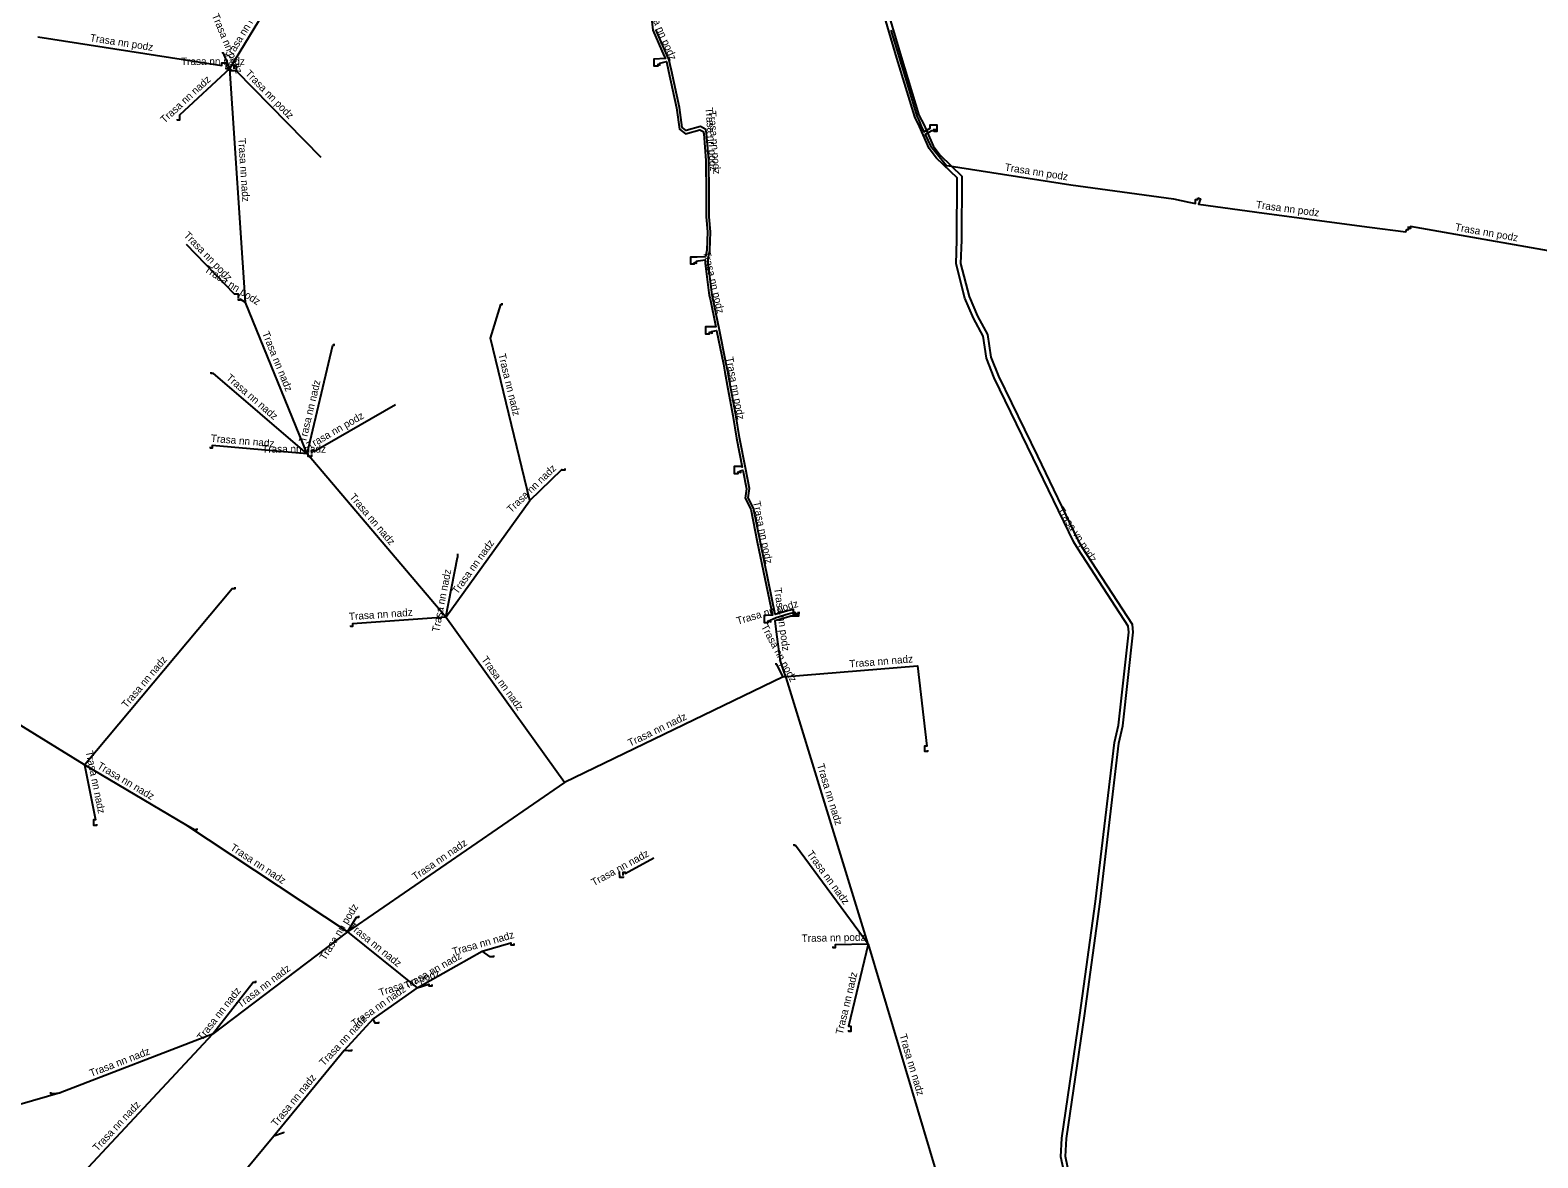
# Model space of a CAD drawing. Extents: x -742082 to -717476, y -1040737 to -1024597.
# Drawn here: x -736206.3 to -736004.4, y -1032268.1 to -1032117.1 of the extents above; entities that cross this region are included whole.
import ezdxf

# ---------------------------------------------------------------- set-up
doc = ezdxf.new("R2010")
doc.units = 0
for name, color, linetype in [('Level 13', 7, 'Continuous'), ('Level 14', 7, 'Continuous'), ('Level 15', 7, 'Continuous'), ('Level 20', 7, 'Continuous'), ('Level 25', 7, 'Continuous')]:
    doc.layers.add(name, color=color, linetype=linetype)

msp = doc.modelspace()

# ---------------------------------------------------------------- linework, layer by layer
at = {"layer": 'Level 13'}
for p, q in [((-736177.51, -1032153.54), (-736179.61, -1032122.24)), ((-736169.24, -1032173.82), (-736177.51, -1032153.54)), ((-736150.66, -1032195.7), (-736169.24, -1032173.82)), ((-736150.66, -1032195.7), (-736149.1, -1032187.7)), ((-736134.77, -1032217.84), (-736150.66, -1032195.7)), ((-736105.47, -1032203.68), (-736134.77, -1032217.84)), ((-736094.1, -1032239.5), (-736105.11, -1032203.78)), ((-736134.77, -1032217.84), (-736163.82, -1032237.82)), ((-736163.82, -1032237.82), (-736181.93, -1032251.54)), ((-736094.1, -1032239.5), (-736083.14, -1032276.17)), ((-736181.93, -1032251.54), (-736203.41, -1032274.54))]:
    msp.add_line(p, q, dxfattribs=at)
for points in [[(-736179.61, -1032122.24), (-736179.84, -1032122.11), (-736179.84, -1032122.26), (-736180.1, -1032122.26), (-736180.1, -1032122.1)], [(-736179, -1032122.4), (-736179, -1032122.56), (-736179.35, -1032122.56), (-736179.61, -1032122.24)], [(-736169.24, -1032173.82), (-736169.15, -1032173.8), (-736169.15, -1032174.16), (-736168.6, -1032174.16), (-736168.6, -1032173.9)], [(-736149.1, -1032187.2), (-736149.1, -1032187.36), (-736149.1, -1032187.7)], [(-736184, -1032224), (-736184, -1032224.16), (-736184.31, -1032224.16), (-736185.5, -1032223.5)], [(-736126.9, -1032230.4), (-736126.9, -1032230.57), (-736127.35, -1032230.56), (-736127.4, -1032229.77)], [(-736144.3, -1032241), (-736144.3, -1032241.16), (-736144.75, -1032241.16), (-736145.8, -1032240.4)], [(-736159.7, -1032249.9), (-736159.7, -1032250.06), (-736160.15, -1032250.06), (-736160.4, -1032249.5)], [(-736163.3, -1032253.6), (-736163.3, -1032253.76), (-736163.75, -1032253.76), (-736164.3, -1032253.7)], [(-736203.6, -1032259.3), (-736203.6, -1032259.46), (-736203.34, -1032259.46), (-736202.3, -1032259.4)], [(-736172.4, -1032264.6), (-736172.4, -1032264.76), (-736173.7, -1032265.2)]]:
    msp.add_lwpolyline(points, dxfattribs=at)
at = {"layer": 'Level 14'}
for p, q in [((-736179.61, -1032122.24), (-736172.05, -1032109.83)), ((-736150.66, -1032195.7), (-736139.42, -1032180.08)), ((-736199.06, -1032215.49), (-736219.52, -1032202.89)), ((-736185.5, -1032223.5), (-736199.06, -1032215.49)), ((-736163.82, -1032237.82), (-736185.5, -1032223.5)), ((-736163.82, -1032237.82), (-736154.51, -1032245.34)), ((-736154.51, -1032245.34), (-736145.8, -1032240.4)), ((-736154.51, -1032245.34), (-736160.4, -1032249.5)), ((-736160.4, -1032249.5), (-736164.3, -1032253.7)), ((-736181.93, -1032251.54), (-736202.3, -1032259.4)), ((-736164.3, -1032253.7), (-736173.7, -1032265.2))]:
    msp.add_line(p, q, dxfattribs=at)
for points in [[(-736179.61, -1032122.24), (-736186.34, -1032128.47), (-736186.34, -1032129.16), (-736186.6, -1032129.16), (-736186.6, -1032129)], [(-736139.42, -1032180.08), (-736144.69, -1032158.33), (-736143.31, -1032153.83), (-736143.1, -1032153.83), (-736143.1, -1032153.67)], [(-736169.24, -1032173.82), (-736165.79, -1032159.26), (-736165.6, -1032159.26), (-736165.6, -1032159.1)], [(-736169.24, -1032173.82), (-736181.84, -1032163.01), (-736181.84, -1032163.06), (-736182.1, -1032163.06), (-736182.1, -1032162.9)], [(-736169.24, -1032173.82), (-736181.95, -1032172.73), (-736181.95, -1032173.06), (-736182.2, -1032173.06), (-736182.2, -1032172.9)], [(-736139.42, -1032180.08), (-736135.15, -1032175.94), (-736135.15, -1032175.96), (-736134.7, -1032175.96), (-736134.7, -1032175.8)], [(-736199.06, -1032215.49), (-736179.3, -1032191.86), (-736178.9, -1032191.86), (-736178.9, -1032191.7)], [(-736150.66, -1032195.7), (-736163.15, -1032196.58), (-736163.15, -1032196.96), (-736163.4, -1032196.96), (-736163.4, -1032196.8)], [(-736105.47, -1032203.68), (-736087.5, -1032202.2), (-736086.24, -1032212.95), (-736086.55, -1032212.95), (-736086.55, -1032213.66), (-736086.1, -1032213.66), (-736086.1, -1032213.5)], [(-736199.06, -1032215.49), (-736197.57, -1032222.85), (-736197.85, -1032222.85), (-736197.85, -1032223.56), (-736197.4, -1032223.56), (-736197.4, -1032223.4)], [(-736094.1, -1032239.5), (-736103.84, -1032226.26), (-736104, -1032226.26), (-736104, -1032226.1)], [(-736126.9, -1032230.29), (-736126.9, -1032229.85), (-736126.64, -1032229.85), (-736126.64, -1032230), (-736122.8, -1032227.9)], [(-736145.8, -1032240.4), (-736141.95, -1032239.3), (-736141.95, -1032239.56), (-736141.5, -1032239.56), (-736141.5, -1032239.4)], [(-736094.1, -1032239.5), (-736096.72, -1032250.45), (-736096.44, -1032250.45), (-736096.44, -1032251.16), (-736096.7, -1032251.16), (-736096.7, -1032251)], [(-736181.93, -1032251.54), (-736176.48, -1032244.56), (-736176.1, -1032244.56), (-736176.1, -1032244.4)], [(-736202.3, -1032259.4), (-736215.15, -1032263.1), (-736215.15, -1032263.56), (-736215.4, -1032263.56), (-736215.4, -1032263.4)], [(-736173.7, -1032265.2), (-736183.61, -1032277.15), (-736183.55, -1032277.15), (-736183.55, -1032277.86), (-736183.8, -1032277.86), (-736183.8, -1032277.7)]]:
    msp.add_lwpolyline(points, dxfattribs=at)
at = {"layer": 'Level 15'}
for points in [[(-736123.53, -1032114.91), (-736123.18, -1032115.07), (-736122.95, -1032117.1), (-736121.44, -1032120.56), (-736121.26, -1032120.9), (-736122.79, -1032120.96), (-736122.79, -1032121.87), (-736122.24, -1032121.87), (-736122.24, -1032121.61)], [(-736103.46, -1032194.96), (-736103.46, -1032195.42), (-736104.12, -1032195.42), (-736104.12, -1032194.65), (-736104.93, -1032194.85), (-736106.57, -1032195.34), (-736109.46, -1032181.1), (-736110.18, -1032179.7), (-736109.98, -1032178.48), (-736110.53, -1032175.71), (-736111.35, -1032171.66), (-736111.82, -1032168.61), (-736112.49, -1032165.06), (-736112.92, -1032162.8), (-736113.11, -1032161.76), (-736114.08, -1032157.05), (-736114.89, -1032153), (-736115, -1032152.55), (-736115.53, -1032148.3), (-736115.53, -1032147.63), (-736115.33, -1032146.61), (-736115.22, -1032144.08), (-736115.41, -1032142.09), (-736115.42, -1032139.01), (-736115.46, -1032134.51), (-736115.74, -1032130.92), (-736115.86, -1032130.39), (-736116.58, -1032129.99), (-736118.5, -1032130.54), (-736119.01, -1032130.14), (-736119.38, -1032127.44), (-736120.45, -1032122.5), (-736120.78, -1032120.96), (-736121.07, -1032120.39), (-736122.56, -1032116.99)], [(-736091.09, -1032117.08), (-736089.16, -1032123.38), (-736087.59, -1032128.59), (-736087.33, -1032129.16), (-736087.01, -1032129.93), (-736086.64, -1032130.71), (-736085.81, -1032130.23), (-736085.81, -1032129.76), (-736084.89, -1032129.76), (-736084.89, -1032130.67), (-736085.27, -1032130.67), (-736085.27, -1032130.3)], [(-736205.3, -1032118), (-736180.65, -1032121.83), (-736180.65, -1032121.45), (-736180.1, -1032121.45), (-736180.1, -1032121.99)], [(-736179.61, -1032122.24), (-736180.46, -1032120.19), (-736180.51, -1032120.19), (-736180.51, -1032120.03)], [(-736122.24, -1032121.61), (-736121.99, -1032121.77), (-736121.99, -1032121.52), (-736121.12, -1032121.27), (-736120.84, -1032122.58), (-736119.77, -1032127.51), (-736119.38, -1032130.35), (-736118.58, -1032130.98), (-736116.63, -1032130.42), (-736116.21, -1032130.66), (-736116.13, -1032130.98), (-736115.86, -1032134.53), (-736115.82, -1032139.02), (-736115.81, -1032142.11), (-736115.62, -1032144.09), (-736115.72, -1032146.57), (-736115.89, -1032147.43), (-736117, -1032147.49), (-736117.91, -1032147.49), (-736117.9, -1032148.4), (-736117.36, -1032148.4), (-736117.35, -1032148.14)], [(-736179, -1032122.29), (-736179, -1032121.85), (-736178.74, -1032121.85), (-736178.74, -1032122.56), (-736178.74, -1032122.56), (-736167.4, -1032134.1)], [(-736085.2, -1032130.3), (-736085.2, -1032130.57), (-736085.58, -1032130.57), (-736086.46, -1032131.07), (-736085.74, -1032132.58), (-736083.6, -1032135.23), (-736083.25, -1032135.26), (-736066.96, -1032137.8), (-736053.2, -1032139.68), (-736051.15, -1032140.13), (-736050.27, -1032140.31), (-736050.28, -1032139.79), (-736049.98, -1032139.79), (-736049.98, -1032139.53)], [(-736049.98, -1032139.53), (-736049.62, -1032139.69), (-736049.87, -1032140.38), (-736041.09, -1032141.58), (-736026.98, -1032143.47), (-736022.09, -1032144.11), (-736021.99, -1032143.77), (-736021.75, -1032143.77), (-736021.75, -1032143.4)], [(-735997.22, -1032146.99), (-735997.22, -1032147.26), (-735997.65, -1032147.26), (-735997.7, -1032147.57), (-736021.5, -1032143.37), (-736021.5, -1032143.67), (-736021.67, -1032143.67), (-736021.67, -1032143.4)], [(-736178.45, -1032152.97), (-736178.45, -1032152.43), (-736178.98, -1032152.43), (-736185.4, -1032145.8)], [(-736117.35, -1032148.14), (-736117.1, -1032148.3), (-736117.1, -1032148.04), (-736116.88, -1032147.97), (-736115.93, -1032147.84), (-736115.93, -1032148.32), (-736115.39, -1032152.62), (-736115.28, -1032153.08), (-736114.51, -1032156.84), (-736115.9, -1032156.84), (-736115.9, -1032157.75), (-736115.35, -1032157.75), (-736115.35, -1032157.49)], [(-736177.51, -1032153.54), (-736178.19, -1032153.1), (-736178.19, -1032153.23), (-736178.45, -1032153.23), (-736178.45, -1032153.08)], [(-736115.35, -1032157.49), (-736115, -1032157.65), (-736115.1, -1032157.43), (-736114.43, -1032157.32), (-736113.5, -1032161.84), (-736113.32, -1032162.88), (-736112.89, -1032165.13), (-736112.21, -1032168.68), (-736111.75, -1032171.73), (-736110.96, -1032175.61), (-736111.15, -1032175.53), (-736112.06, -1032175.53), (-736112.06, -1032176.44), (-736111.51, -1032176.44), (-736111.51, -1032176.18)], [(-736168.6, -1032173.79), (-736168.6, -1032173.35), (-736168.35, -1032173.35), (-736168.35, -1032173.5), (-736157.4, -1032167.2)], [(-736111.51, -1032176.18), (-736111.15, -1032176.34), (-736111.25, -1032176.1), (-736110.88, -1032176), (-736110.39, -1032178.49), (-736110.6, -1032179.77), (-736109.84, -1032181.24), (-736108.96, -1032185.59), (-736106.94, -1032195.42), (-736108.04, -1032195.49), (-736108.04, -1032196.4), (-736107.49, -1032196.4), (-736107.49, -1032196.14)], [(-736107.49, -1032196.14), (-736107.14, -1032196.3), (-736107.23, -1032196.09), (-736106.45, -1032195.72), (-736104.82, -1032195.24), (-736103.92, -1032195.01), (-736103.92, -1032195.22), (-736103.36, -1032195.22), (-736103.36, -1032194.96)], [(-736103.44, -1032194.96), (-736103.44, -1032195.57), (-736103.61, -1032195.57), (-736104.48, -1032195.57), (-736104.72, -1032195.63), (-736106.62, -1032196.19), (-736106.38, -1032198), (-736105.89, -1032201.6), (-736105.44, -1032202.94), (-736105.22, -1032203.57), (-736105.11, -1032203.78)], [(-736105.47, -1032203.68), (-736106.35, -1032202.02), (-736106.45, -1032202.02), (-736106.45, -1032201.86)], [(-736163.82, -1032237.82), (-736162.62, -1032235.86), (-736162.3, -1032235.86), (-736162.3, -1032235.7)], [(-736094.1, -1032239.5), (-736098.54, -1032239.59), (-736098.54, -1032239.96), (-736098.8, -1032239.96), (-736098.8, -1032239.8)], [(-736154.51, -1032245.34), (-736152.95, -1032244.82), (-736152.95, -1032245.06), (-736152.5, -1032245.06), (-736152.5, -1032244.9)]]:
    msp.add_lwpolyline(points, dxfattribs=at)
at = {"layer": 'Level 25'}
for points in [[(-736067.77, -1032270.43), (-736068.3, -1032267.95), (-736068.15, -1032265.46), (-736065.74, -1032249), (-736063.65, -1032233.75), (-736061.14, -1032212.46), (-736060.58, -1032210.15), (-736059.22, -1032197.72), (-736059.3, -1032196.89), (-736066, -1032186.61), (-736066.55, -1032185.67), (-736071.99, -1032174.41), (-736077.22, -1032163.66), (-736078.25, -1032161.03), (-736078.7, -1032158.05), (-736080.02, -1032155.68), (-736081.18, -1032152.96), (-736082.34, -1032148.4), (-736082.24, -1032145.22), (-736082.18, -1032136.89), (-736084.94, -1032134.23), (-736085.92, -1032132.92), (-736087.23, -1032129.99), (-736087.87, -1032128.7), (-736090.27, -1032120.85), (-736092.54, -1032113.13)], [(-736091.95, -1032112.95), (-736089.69, -1032120.67), (-736087.3, -1032128.47), (-736086.67, -1032129.73), (-736085.39, -1032132.6), (-736084.48, -1032133.82), (-736081.57, -1032136.63), (-736081.63, -1032145.23), (-736081.73, -1032148.33), (-736080.6, -1032152.76), (-736079.47, -1032155.41), (-736078.11, -1032157.85), (-736077.66, -1032160.87), (-736076.67, -1032163.41), (-736071.45, -1032174.15), (-736066.02, -1032185.39), (-736065.49, -1032186.3)], [(-736067.19, -1032270.26), (-736067.69, -1032267.9), (-736067.55, -1032265.52), (-736065.15, -1032249.09), (-736063.05, -1032233.82), (-736060.55, -1032212.57), (-736059.99, -1032210.25), (-736058.61, -1032197.72), (-736058.72, -1032196.69), (-736065.49, -1032186.3)]]:
    msp.add_lwpolyline(points, dxfattribs=at)

# ---------------------------------------------------------------- texts
at = {"layer": 'Level 20'}
for s, rotation, p in [('Trasa nn nadz', 58.6505, (-736179.53, -1032121.15)), ('Trasa nn podz', 293.5564, (-736124.01, -1032113.41)), ('Trasa nn podz', 292.5787, (-736182.03, -1032115.12)), ('Trasa nn podz', 351.1681, (-736198.38, -1032118.57)), ('Trasa nn nadz', 360, (-736186.13, -1032121.76)), ('Trasa nn nadz', 42.7765, (-736188.34, -1032129.63)), ('Trasa nn podz', 314.5145, (-736177.62, -1032122.99)), ('Trasa nn podz', 274.3455, (-736115.9, -1032127.49)), ('Trasa nn podz', 274.3462, (-736115.47, -1032127.91)), ('Trasa nn nadz', 273.8384, (-736178.48, -1032131.58)), ('Trasa nn podz', 351.1286, (-736075.87, -1032135.9)), ('Trasa nn podz', 352.3782, (-736042.22, -1032140.92)), ('Trasa nn podz', 314.087, (-736185.83, -1032144.64)), ('Trasa nn podz', 350.0101, (-736015.57, -1032143.91)), ('Trasa nn podz', 283.0678, (-736116.23, -1032146.8)), ('Trasa nn podz', 327.343, (-736183.1, -1032149.36)), ('Trasa nn nadz', 292.1852, (-736175.29, -1032157.67)), ('Trasa nn nadz', 283.6202, (-736143.65, -1032160.51)), ('Trasa nn podz', 280.7374, (-736113.17, -1032160.94)), ('Trasa nn nadz', 319.3695, (-736180.17, -1032163.79)), ('Trasa nn nadz', 76.6525, (-736169.41, -1032172.37)), ('Trasa nn podz', 29.9083, (-736168.94, -1032173.26)), ('Trasa nn nadz', 355.0984, (-736182.18, -1032172.21)), ('Trasa nn nadz', 44.1187, (-736141.92, -1032181.81)), ('Trasa nn nadz', 310.3372, (-736163.64, -1032179.64)), ('Trasa nn podz', 281.5863, (-736109.54, -1032180.26)), ('Trasa vn podz', 303.0777, (-736068.83, -1032181.35)), ('Trasa nn nadz', 54.2616, (-736149.12, -1032192.7)), ('Trasa nn nadz', 78.9658, (-736151.57, -1032197.77)), ('Trasa nn podz', 277.7247, (-736106.71, -1032191.82)), ('Trasa nn podz', 16.3249, (-736111.58, -1032196.7)), ('Trasa nn nadz', 4.0096, (-736163.61, -1032196.11)), ('Trasa nn podz', 298.0319, (-736108.48, -1032196.95)), ('Trasa nn nadz', 50.0982, (-736193.42, -1032207.96)), ('Trasa nn nadz', 305.6672, (-736145.97, -1032201.37)), ('Trasa nn nadz', 4.7117, (-736096.59, -1032202.45)), ('Trasa nn nadz', 25.791, (-736126, -1032213.05)), ('Trasa nn nadz', 281.4385, (-736198.91, -1032213.69)), ('Trasa nn nadz', 329.4293, (-736197.44, -1032215.87)), ('Trasa nn nadz', 287.1279, (-736100.98, -1032215.48)), ('Trasa nn nadz', 326.5546, (-736179.63, -1032226.78)), ('Trasa nn nadz', 34.5194, (-736154.76, -1032230.98)), ('Trasa nn nadz', 28.7061, (-736130.85, -1032231.74)), ('Trasa nn nadz', 306.3268, (-736102.39, -1032227.39)), ('Trasa nn podz', 58.5305, (-736166.8, -1032241.74)), ('Trasa nn nadz', 321.071, (-736163.74, -1032237.24)), ('Trasa nn nadz', 15.9454, (-736149.64, -1032240.98)), ('Trasa nn podz', 1.1932, (-736103.01, -1032239.19)), ('Trasa nn nadz', 29.5604, (-736155.87, -1032245.54)), ('Trasa nn nadz', 37.1473, (-736178.19, -1032248.08)), ('Trasa nn podz', 18.5258, (-736159.45, -1032246.47)), ('Trasa nn nadz', 76.5618, (-736097.52, -1032251.65)), ('Trasa nn nadz', 52.0225, (-736183.3, -1032252.48)), ('Trasa nn nadz', 35.2329, (-736162.88, -1032250.64)), ('Trasa nn nadz', 47.1211, (-736166.99, -1032255.87)), ('Trasa nn nadz', 286.6405, (-736089.94, -1032251.67)), ('Trasa nn nadz', 21.0997, (-736198.16, -1032257.27)), ('Trasa nn nadz', 50.7377, (-736173.37, -1032264)), ('Trasa nn nadz', 46.9572, (-736197.33, -1032267.29))]:
    msp.add_text(s, height=1, rotation=rotation, dxfattribs=at).set_placement(p)
msp.add_text('Trasa nn nadz', height=1, dxfattribs=at).set_placement((-736175.26, -1032173.66))

doc.saveas('drawing.dxf')
